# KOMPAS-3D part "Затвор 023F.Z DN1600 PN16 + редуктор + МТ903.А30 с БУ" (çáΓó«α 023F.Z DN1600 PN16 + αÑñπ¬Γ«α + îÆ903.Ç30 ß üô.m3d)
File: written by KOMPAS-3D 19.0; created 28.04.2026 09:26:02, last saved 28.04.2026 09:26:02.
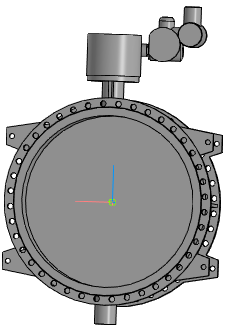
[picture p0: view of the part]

Document properties: Автор: Энергия; Полное имя файла: ..\Затвор 023F.Z DN1600 PN16 + редуктор + МТ903.А30.a3d

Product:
- Part/product: Затвор 023F.Z DN1600 PN16 + редуктор + МТ903.А30 с БУ
    Масса: 4741.91

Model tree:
1. Операция без истории:1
